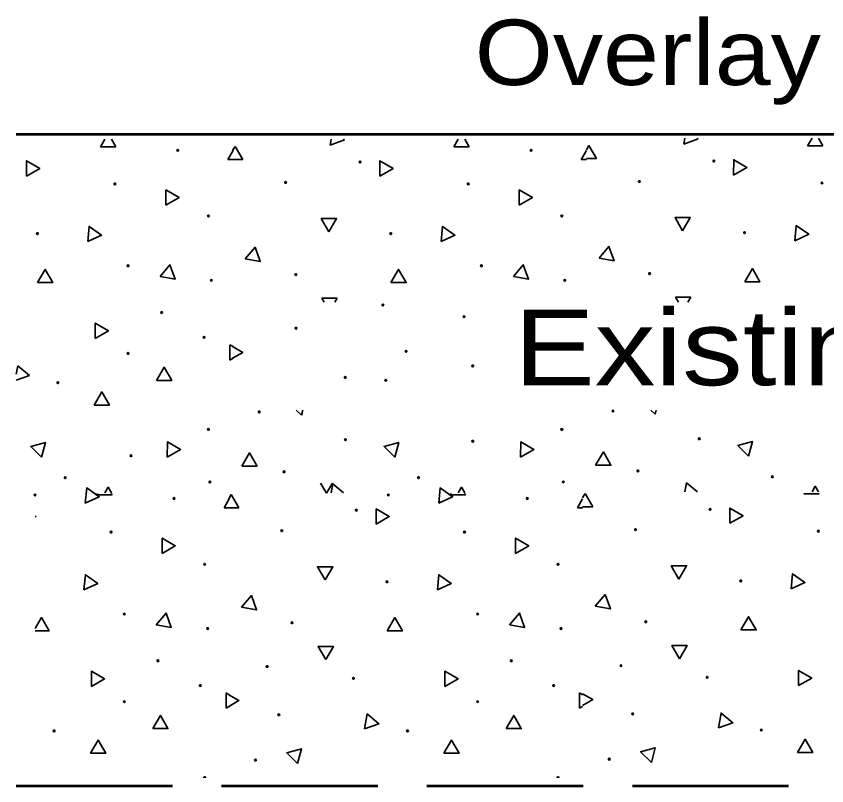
# Model space of a CAD drawing. Extents: x 72.6 to 107.3, y 36.1 to 58.1.
# Drawn here: x 90.018 to 91.667, y 53.319 to 54.886 of the extents above; entities that cross this region are included whole.
import ezdxf

# ---------------------------------------------------------------- set-up
doc = ezdxf.new("R2010")
doc.units = 0
doc.header["$LTSCALE"] = 0.053
doc.linetypes.add('LONG_DASHED', pattern=[7.5, 6, -1.5])
doc.layers.add('1', color=7, linetype='Continuous', lineweight=35)
doc.layers.add('3', color=7, linetype='Continuous', lineweight=13)

msp = doc.modelspace()

# ---------------------------------------------------------------- linework, layer by layer
at = {"layer": '1', "lineweight": 53}
msp.add_line((90.01767, 54.64575), (94.0285, 54.64575), dxfattribs=at)
at = {"layer": '1'}
for p, q in [((91.37875, 54.63742), (91.37658, 54.62525)), ((91.37875, 54.63742), (91.37658, 54.62525)), ((91.40575, 54.63592), (91.40392, 54.63742)), ((91.40575, 54.63592), (91.40392, 54.63742)), ((91.63742, 54.63742), (91.62842, 54.622)), ((91.63742, 54.63742), (91.62842, 54.622)), ((91.65958, 54.622), (91.65058, 54.63742)), ((91.65958, 54.622), (91.65058, 54.63742)), ((90.19825, 54.6355), (90.18925, 54.62008)), ((90.19825, 54.6355), (90.18925, 54.62008)), ((90.22042, 54.62008), (90.21142, 54.6355)), ((90.22042, 54.62008), (90.21142, 54.6355)), ((90.46308, 54.62067), (90.45808, 54.612)), ((90.46308, 54.62067), (90.45808, 54.612)), ((90.47858, 54.59383), (90.46308, 54.62067)), ((90.47858, 54.59383), (90.46308, 54.62067)), ((90.65875, 54.6355), (90.65658, 54.62333)), ((90.65875, 54.6355), (90.65658, 54.62333)), ((90.65658, 54.62333), (90.68575, 54.634)), ((90.65658, 54.62333), (90.68575, 54.634)), ((90.68575, 54.634), (90.68392, 54.6355)), ((90.68575, 54.634), (90.68392, 54.6355)), ((90.91742, 54.6355), (90.90842, 54.62008)), ((90.91742, 54.6355), (90.90842, 54.62008)), ((90.93958, 54.62008), (90.93058, 54.6355)), ((90.93958, 54.62008), (90.93058, 54.6355)), ((91.18308, 54.62258), (91.17808, 54.61392)), ((91.18308, 54.62258), (91.17808, 54.61392)), ((91.19858, 54.59575), (91.18308, 54.62258)), ((91.19858, 54.59575), (91.18308, 54.62258)), ((91.37658, 54.62525), (91.40575, 54.63592)), ((91.37658, 54.62525), (91.40575, 54.63592)), ((91.62842, 54.622), (91.65958, 54.622)), ((91.62842, 54.622), (91.65958, 54.622)), ((90.18925, 54.62008), (90.22042, 54.62008)), ((90.18925, 54.62008), (90.22042, 54.62008)), ((90.45892, 54.612), (90.44833, 54.59383)), ((90.45892, 54.612), (90.44833, 54.59383)), ((90.90842, 54.62008), (90.93958, 54.62008)), ((90.90842, 54.62008), (90.93958, 54.62008)), ((91.17808, 54.612), (91.1675, 54.59383)), ((91.17808, 54.612), (91.1675, 54.59383)), ((90.44833, 54.59383), (90.45892, 54.59383)), ((90.44833, 54.59383), (90.45892, 54.59383)), ((90.45808, 54.59383), (90.47858, 54.59383)), ((90.45808, 54.59383), (90.47858, 54.59383)), ((91.1675, 54.59383), (91.17808, 54.59383)), ((91.1675, 54.59383), (91.17808, 54.59383)), ((91.17808, 54.59575), (91.19858, 54.59575)), ((91.17808, 54.59575), (91.19858, 54.59575)), ((90.67075, 54.31158), (90.63967, 54.31158)), ((90.63967, 54.31158), (90.64442, 54.30333)), ((90.67075, 54.31158), (90.63967, 54.31158)), ((90.63967, 54.31158), (90.64442, 54.30333)), ((90.666, 54.30333), (90.67075, 54.31158)), ((90.666, 54.30333), (90.67075, 54.31158)), ((91.39075, 54.3135), (91.35967, 54.3135)), ((91.35967, 54.3135), (91.3655, 54.30333)), ((91.39075, 54.3135), (91.35967, 54.3135)), ((91.35967, 54.3135), (91.3655, 54.30333)), ((91.38483, 54.30333), (91.39075, 54.3135)), ((91.38483, 54.30333), (91.39075, 54.3135)), ((90.45275, 54.21683), (90.45258, 54.18575)), ((90.45275, 54.21683), (90.45258, 54.18575)), ((90.45275, 54.21683), (90.45258, 54.18575)), ((90.45275, 54.21683), (90.45258, 54.18575)), ((90.45892, 54.21325), (90.45275, 54.21683)), ((90.45892, 54.21325), (90.45275, 54.21683)), ((90.45892, 54.21325), (90.45275, 54.21683)), ((90.45892, 54.21325), (90.45275, 54.21683)), ((90.45258, 54.18575), (90.45892, 54.18933)), ((90.45258, 54.18575), (90.45892, 54.18933)), ((90.45258, 54.18575), (90.45892, 54.18933)), ((90.45258, 54.18575), (90.45892, 54.18933)), ((90.02075, 54.17417), (90.01767, 54.15683)), ((90.02075, 54.17417), (90.01767, 54.15683)), ((90.0445, 54.15433), (90.02075, 54.17417)), ((90.0445, 54.15433), (90.02075, 54.17417)), ((90.01767, 54.1445), (90.0445, 54.15433)), ((90.01767, 54.1445), (90.0445, 54.15433)), ((90.58733, 54.084), (90.598, 54.07333)), ((90.58733, 54.084), (90.598, 54.07333)), ((90.598, 54.07333), (90.60083, 54.084)), ((90.598, 54.07333), (90.60083, 54.084)), ((91.30925, 54.084), (91.318, 54.07525)), ((91.30925, 54.084), (91.318, 54.07525)), ((91.318, 54.07525), (91.32033, 54.084)), ((91.318, 54.07525), (91.32033, 54.084)), ((90.63708, 53.93542), (90.649, 53.91467)), ((90.63708, 53.93542), (90.649, 53.91467)), ((90.649, 53.91467), (90.66108, 53.93542)), ((90.649, 53.91467), (90.66108, 53.93542)), ((90.18342, 53.91433), (90.18158, 53.91125)), ((90.18342, 53.91433), (90.18158, 53.91125)), ((90.18342, 53.91433), (90.18158, 53.91125)), ((90.18342, 53.91433), (90.18158, 53.91125)), ((90.18158, 53.91125), (90.21275, 53.91125)), ((90.18158, 53.91125), (90.21275, 53.91125)), ((90.18158, 53.91125), (90.21275, 53.91125)), ((90.18158, 53.91125), (90.21275, 53.91125)), ((90.21275, 53.91125), (90.21092, 53.91433)), ((90.21275, 53.91125), (90.21092, 53.91433)), ((90.21275, 53.91125), (90.21092, 53.91433)), ((90.21275, 53.91125), (90.21092, 53.91433)), ((90.45542, 53.91183), (90.45042, 53.90317)), ((90.45542, 53.91183), (90.45042, 53.90317)), ((90.47092, 53.885), (90.45542, 53.91183)), ((90.47092, 53.885), (90.45542, 53.91183)), ((90.90258, 53.91433), (90.90075, 53.91125)), ((90.90258, 53.91433), (90.90075, 53.91125)), ((90.90075, 53.91125), (90.93192, 53.91125)), ((90.90075, 53.91125), (90.93192, 53.91125)), ((90.93192, 53.91125), (90.93008, 53.91433)), ((90.93192, 53.91125), (90.93008, 53.91433)), ((91.17542, 53.91375), (91.17042, 53.90508)), ((91.17542, 53.91375), (91.17042, 53.90508)), ((91.19092, 53.88692), (91.17542, 53.91375)), ((91.19092, 53.88692), (91.17542, 53.91375)), ((91.62142, 53.91433), (91.62075, 53.91317)), ((91.62142, 53.91433), (91.62075, 53.91317)), ((91.62075, 53.91317), (91.65192, 53.91317)), ((91.62075, 53.91317), (91.65192, 53.91317)), ((91.65192, 53.91317), (91.65125, 53.91433)), ((91.65192, 53.91317), (91.65125, 53.91433)), ((90.45125, 53.90317), (90.44067, 53.885)), ((90.45125, 53.90317), (90.44067, 53.885)), ((90.45125, 53.90317), (90.44067, 53.885)), ((90.45125, 53.90317), (90.44067, 53.885)), ((91.17042, 53.90317), (91.15983, 53.885)), ((91.17042, 53.90317), (91.15983, 53.885)), ((90.44067, 53.885), (90.45125, 53.885)), ((90.44067, 53.885), (90.45125, 53.885)), ((90.44067, 53.885), (90.45125, 53.885)), ((90.44067, 53.885), (90.45125, 53.885)), ((90.45042, 53.885), (90.47092, 53.885)), ((90.45042, 53.885), (90.47092, 53.885)), ((91.15983, 53.885), (91.17042, 53.885)), ((91.15983, 53.885), (91.17042, 53.885)), ((91.17042, 53.88692), (91.19092, 53.88692)), ((91.17042, 53.88692), (91.19092, 53.88692)), ((90.44508, 53.508), (90.44492, 53.47692)), ((90.44508, 53.508), (90.44492, 53.47692)), ((90.44508, 53.508), (90.44492, 53.47692)), ((90.44508, 53.508), (90.44492, 53.47692)), ((90.44508, 53.508), (90.44492, 53.47692)), ((90.44508, 53.508), (90.44492, 53.47692)), ((90.44508, 53.508), (90.44492, 53.47692)), ((90.44508, 53.508), (90.44492, 53.47692)), ((90.45125, 53.50442), (90.44508, 53.508)), ((90.45125, 53.50442), (90.44508, 53.508)), ((90.45125, 53.50442), (90.44508, 53.508)), ((90.45125, 53.50442), (90.44508, 53.508)), ((90.45125, 53.50442), (90.44508, 53.508)), ((90.45125, 53.50442), (90.44508, 53.508)), ((90.45125, 53.50442), (90.44508, 53.508)), ((90.45125, 53.50442), (90.44508, 53.508)), ((91.16425, 53.508), (91.16408, 53.47692)), ((91.16425, 53.508), (91.16408, 53.47692)), ((91.16425, 53.508), (91.16408, 53.47692)), ((91.16425, 53.508), (91.16408, 53.47692)), ((91.17042, 53.50442), (91.16425, 53.508)), ((91.17042, 53.50442), (91.16425, 53.508)), ((91.17042, 53.50442), (91.16425, 53.508)), ((91.17042, 53.50442), (91.16425, 53.508)), ((90.44492, 53.47692), (90.45125, 53.4805)), ((90.44492, 53.47692), (90.45125, 53.4805)), ((90.44492, 53.47692), (90.45125, 53.4805)), ((90.44492, 53.47692), (90.45125, 53.4805)), ((90.44492, 53.47692), (90.45125, 53.4805)), ((90.44492, 53.47692), (90.45125, 53.4805)), ((90.44492, 53.47692), (90.45125, 53.4805)), ((90.44492, 53.47692), (90.45125, 53.4805)), ((91.16408, 53.47692), (91.17042, 53.4805)), ((91.16408, 53.47692), (91.17042, 53.4805)), ((91.16408, 53.47692), (91.17042, 53.4805)), ((91.16408, 53.47692), (91.17042, 53.4805))]:
    msp.add_line(p, q, dxfattribs=at)
at = {"layer": '1', "linetype": 'LONG_DASHED', "lineweight": 53}
msp.add_line((90.01767, 53.31908), (94.0285, 53.31908), dxfattribs=at)
msp.add_line((90.01767, 53.31908), (94.0285, 53.31908), dxfattribs=at)
at = {"layer": '1', "lineweight": 53}
msp.add_lwpolyline([(90.01767, 54.64575), (94.0285, 54.64575), (97.54775, 54.52283)], dxfattribs=at)
msp.add_lwpolyline([(90.01767, 54.64575), (94.0285, 54.64575), (97.54775, 54.52283)], dxfattribs=at)
at = {"layer": '1'}
for points in [[(90.03858, 54.56033), (90.0655, 54.57583), (90.03875, 54.59142)], [(90.03858, 54.56033), (90.0655, 54.57583), (90.03875, 54.59142)], [(90.75775, 54.56033), (90.78467, 54.57583), (90.75792, 54.59142)], [(90.75775, 54.56033), (90.78467, 54.57583), (90.75792, 54.59142)], [(91.47775, 54.56225), (91.50467, 54.57775), (91.47792, 54.59333)], [(91.47775, 54.56225), (91.50467, 54.57775), (91.47792, 54.59333)], [(90.32225, 54.50083), (90.34917, 54.51642), (90.32242, 54.532)], [(90.32225, 54.50083), (90.34917, 54.51642), (90.32242, 54.532)], [(91.04142, 54.50083), (91.06833, 54.51642), (91.04158, 54.532)], [(91.04142, 54.50083), (91.06833, 54.51642), (91.04158, 54.532)], [(90.65392, 54.44692), (90.66958, 54.47383), (90.6385, 54.47383)], [(90.65392, 54.44692), (90.66958, 54.47383), (90.6385, 54.47383)], [(91.37392, 54.44883), (91.38958, 54.47575), (91.3585, 54.47575)], [(91.37392, 54.44883), (91.38958, 54.47575), (91.3585, 54.47575)], [(90.16325, 54.42675), (90.19142, 54.43983), (90.16608, 54.45767)], [(90.16325, 54.42675), (90.19142, 54.43983), (90.16608, 54.45767)], [(90.88242, 54.42675), (90.91058, 54.43983), (90.88525, 54.45767)], [(90.88242, 54.42675), (90.91058, 54.43983), (90.88525, 54.45767)], [(91.60242, 54.42867), (91.63058, 54.44175), (91.60525, 54.45958)], [(91.60242, 54.42867), (91.63058, 54.44175), (91.60525, 54.45958)], [(90.48392, 54.3915), (90.5145, 54.38608), (90.50392, 54.41525)], [(90.48392, 54.3915), (90.5145, 54.38608), (90.50392, 54.41525)], [(91.20392, 54.39342), (91.2345, 54.388), (91.22392, 54.41717)], [(91.20392, 54.39342), (91.2345, 54.388), (91.22392, 54.41717)], [(90.31042, 54.35575), (90.34092, 54.35033), (90.33033, 54.37958)], [(91.02958, 54.35575), (91.06008, 54.35033), (91.0495, 54.37958)], [(91.02958, 54.35575), (91.06008, 54.35033), (91.0495, 54.37958)], [(90.06108, 54.34333), (90.09217, 54.34333), (90.07675, 54.37017)], [(90.06108, 54.34333), (90.09217, 54.34333), (90.07675, 54.37017)], [(90.78025, 54.34333), (90.81133, 54.34333), (90.79592, 54.37017)], [(90.78025, 54.34333), (90.81133, 54.34333), (90.79592, 54.37017)], [(91.50025, 54.34525), (91.53133, 54.34525), (91.51592, 54.37208)], [(91.50025, 54.34525), (91.53133, 54.34525), (91.51592, 54.37208)], [(90.17842, 54.22992), (90.20533, 54.24542), (90.1785, 54.261)], [(90.17842, 54.22992), (90.20533, 54.24542), (90.1785, 54.261)], [(90.30308, 54.14433), (90.33408, 54.14433), (90.31867, 54.17117)], [(90.30308, 54.14433), (90.33408, 54.14433), (90.31867, 54.17117)], [(90.17633, 54.094), (90.20742, 54.094), (90.19192, 54.12083)], [(90.17633, 54.094), (90.20742, 54.094), (90.19192, 54.12083)], [(90.06908, 53.98792), (90.07708, 54.018), (90.04717, 54.01)], [(90.06908, 53.98792), (90.07708, 54.018), (90.04717, 54.01)], [(90.32508, 53.988), (90.35208, 54.0035), (90.32533, 54.019)], [(90.32508, 53.988), (90.35208, 54.0035), (90.32533, 54.019)], [(90.78825, 53.98792), (90.79625, 54.018), (90.76633, 54.01)], [(90.78825, 53.98792), (90.79625, 54.018), (90.76633, 54.01)], [(91.04425, 53.988), (91.07125, 54.0035), (91.0445, 54.019)], [(91.04425, 53.988), (91.07125, 54.0035), (91.0445, 54.019)], [(91.50825, 53.98983), (91.51625, 54.01992), (91.48633, 54.01192)], [(91.50825, 53.98983), (91.51625, 54.01992), (91.48633, 54.01192)], [(90.47692, 53.96983), (90.508, 53.96983), (90.49258, 53.99667)], [(90.47692, 53.96983), (90.508, 53.96983), (90.49258, 53.99667)], [(91.19692, 53.97175), (91.228, 53.97175), (91.21258, 53.99858)], [(91.19692, 53.97175), (91.228, 53.97175), (91.21258, 53.99858)], [(90.15833, 53.8945), (90.1865, 53.90758), (90.16117, 53.92542)], [(90.15833, 53.8945), (90.1865, 53.90758), (90.16117, 53.92542)], [(90.8775, 53.8945), (90.90567, 53.90758), (90.88033, 53.92542)], [(90.8775, 53.8945), (90.90567, 53.90758), (90.88033, 53.92542)], [(90.75008, 53.8515), (90.777, 53.867), (90.75025, 53.88258)], [(90.75008, 53.8515), (90.777, 53.867), (90.75025, 53.88258)], [(91.47008, 53.85342), (91.497, 53.86892), (91.47025, 53.8845)], [(91.47008, 53.85342), (91.497, 53.86892), (91.47025, 53.8845)], [(90.31458, 53.792), (90.3415, 53.80758), (90.31475, 53.82317)], [(90.31458, 53.792), (90.3415, 53.80758), (90.31475, 53.82317)], [(90.31458, 53.792), (90.3415, 53.80758), (90.31475, 53.82317)], [(90.31458, 53.792), (90.3415, 53.80758), (90.31475, 53.82317)], [(91.03375, 53.792), (91.06067, 53.80758), (91.03392, 53.82317)], [(91.03375, 53.792), (91.06067, 53.80758), (91.03392, 53.82317)], [(90.64625, 53.73808), (90.66192, 53.765), (90.63083, 53.765)], [(90.64625, 53.73808), (90.66192, 53.765), (90.63083, 53.765)], [(91.36625, 53.74), (91.38192, 53.76692), (91.35083, 53.76692)], [(91.36625, 53.74), (91.38192, 53.76692), (91.35083, 53.76692)], [(90.15558, 53.71792), (90.18375, 53.731), (90.15842, 53.74883)], [(90.15558, 53.71792), (90.18375, 53.731), (90.15842, 53.74883)], [(90.15558, 53.71792), (90.18375, 53.731), (90.15842, 53.74883)], [(90.15558, 53.71792), (90.18375, 53.731), (90.15842, 53.74883)], [(90.87475, 53.71792), (90.90292, 53.731), (90.87758, 53.74883)], [(90.87475, 53.71792), (90.90292, 53.731), (90.87758, 53.74883)], [(91.59475, 53.71983), (91.62292, 53.73292), (91.59758, 53.75075)], [(91.59475, 53.71983), (91.62292, 53.73292), (91.59758, 53.75075)], [(90.47625, 53.68267), (90.50683, 53.67725), (90.49625, 53.70642)], [(90.47625, 53.68267), (90.50683, 53.67725), (90.49625, 53.70642)], [(91.19625, 53.68458), (91.22683, 53.67917), (91.21625, 53.70833)], [(91.19625, 53.68458), (91.22683, 53.67917), (91.21625, 53.70833)], [(90.30275, 53.64692), (90.33325, 53.6415), (90.32267, 53.67075)], [(90.30275, 53.64692), (90.33325, 53.6415), (90.32267, 53.67075)], [(91.02192, 53.64692), (91.05242, 53.6415), (91.04183, 53.67075)], [(91.02192, 53.64692), (91.05242, 53.6415), (91.04183, 53.67075)], [(90.77258, 53.6345), (90.80367, 53.6345), (90.78825, 53.66133)], [(90.77258, 53.6345), (90.80367, 53.6345), (90.78825, 53.66133)], [(91.49258, 53.63642), (91.52367, 53.63642), (91.50825, 53.66325)], [(91.49258, 53.63642), (91.52367, 53.63642), (91.50825, 53.66325)], [(90.6475, 53.57583), (90.66308, 53.60275), (90.632, 53.60275)], [(90.6475, 53.57583), (90.66308, 53.60275), (90.632, 53.60275)], [(91.3675, 53.57775), (91.38308, 53.60467), (91.352, 53.60467)], [(91.3675, 53.57775), (91.38308, 53.60467), (91.352, 53.60467)], [(90.17075, 53.52108), (90.19767, 53.53658), (90.17083, 53.55217)], [(90.17075, 53.52108), (90.19767, 53.53658), (90.17083, 53.55217)], [(90.17075, 53.52108), (90.19767, 53.53658), (90.17083, 53.55217)], [(90.17075, 53.52108), (90.19767, 53.53658), (90.17083, 53.55217)], [(90.88992, 53.52108), (90.91683, 53.53658), (90.89, 53.55217)], [(90.88992, 53.52108), (90.91683, 53.53658), (90.89, 53.55217)], [(91.60992, 53.523), (91.63683, 53.5385), (91.61, 53.55408)], [(91.60992, 53.523), (91.63683, 53.5385), (91.61, 53.55408)], [(91.44683, 53.43675), (91.476, 53.44742), (91.45225, 53.46725)], [(91.44683, 53.43675), (91.476, 53.44742), (91.45225, 53.46725)], [(90.29542, 53.4355), (90.32642, 53.4355), (90.311, 53.46233)], [(90.29542, 53.4355), (90.32642, 53.4355), (90.311, 53.46233)], [(90.29542, 53.4355), (90.32642, 53.4355), (90.311, 53.46233)], [(90.29542, 53.4355), (90.32642, 53.4355), (90.311, 53.46233)], [(90.72683, 53.43483), (90.756, 53.4455), (90.73225, 53.46533)], [(90.72683, 53.43483), (90.756, 53.4455), (90.73225, 53.46533)], [(91.01458, 53.4355), (91.04558, 53.4355), (91.03017, 53.46233)], [(91.01458, 53.4355), (91.04558, 53.4355), (91.03017, 53.46233)], [(90.16867, 53.38517), (90.19975, 53.38517), (90.18425, 53.412)], [(90.16867, 53.38517), (90.19975, 53.38517), (90.18425, 53.412)], [(90.16867, 53.38517), (90.19975, 53.38517), (90.18425, 53.412)], [(90.16867, 53.38517), (90.19975, 53.38517), (90.18425, 53.412)], [(90.88783, 53.38517), (90.91892, 53.38517), (90.90342, 53.412)], [(90.88783, 53.38517), (90.91892, 53.38517), (90.90342, 53.412)], [(91.60783, 53.38708), (91.63892, 53.38708), (91.62342, 53.41392)], [(91.60783, 53.38708), (91.63892, 53.38708), (91.62342, 53.41392)], [(90.59033, 53.3645), (90.59833, 53.3945), (90.56842, 53.3865)], [(90.59033, 53.3645), (90.59833, 53.3945), (90.56842, 53.3865)], [(91.31033, 53.36642), (91.31833, 53.39642), (91.28842, 53.38842)], [(91.31033, 53.36642), (91.31833, 53.39642), (91.28842, 53.38842)]]:
    msp.add_lwpolyline(points, close=True, dxfattribs=at)
for points in [[(90.31042, 54.35575), (90.34092, 54.35033), (90.33033, 54.37958)], [(90.45808, 54.18933), (90.47867, 54.20133), (90.45808, 54.21325)], [(90.45808, 54.18933), (90.47867, 54.20133), (90.45808, 54.21325)], [(90.68392, 53.9155), (90.66208, 53.93383), (90.65875, 53.9155)], [(90.68392, 53.9155), (90.66208, 53.93383), (90.65875, 53.9155)], [(90.68392, 53.9155), (90.66208, 53.93383), (90.65875, 53.9155)], [(90.68392, 53.9155), (90.66208, 53.93383), (90.65875, 53.9155)], [(91.40392, 53.91742), (91.38208, 53.93575), (91.37875, 53.91742)], [(91.40392, 53.91742), (91.38208, 53.93575), (91.37875, 53.91742)], [(91.40392, 53.91742), (91.38208, 53.93575), (91.37875, 53.91742)], [(91.40392, 53.91742), (91.38208, 53.93575), (91.37875, 53.91742)], [(91.65058, 53.91742), (91.644, 53.92883), (91.63742, 53.91742)], [(91.65058, 53.91742), (91.644, 53.92883), (91.63742, 53.91742)], [(90.21142, 53.9155), (90.20483, 53.92692), (90.19825, 53.9155)], [(90.21142, 53.9155), (90.20483, 53.92692), (90.19825, 53.9155)], [(90.93058, 53.9155), (90.924, 53.92692), (90.91742, 53.9155)], [(90.93058, 53.9155), (90.924, 53.92692), (90.91742, 53.9155)], [(90.05625, 53.86608), (90.05783, 53.867), (90.05625, 53.86792)], [(90.05625, 53.86608), (90.05783, 53.867), (90.05625, 53.86792)], [(90.05625, 53.86608), (90.05783, 53.867), (90.05625, 53.86792)], [(90.05625, 53.86608), (90.05783, 53.867), (90.05625, 53.86792)], [(90.30275, 53.64692), (90.33325, 53.6415), (90.32267, 53.67075)], [(90.30275, 53.64692), (90.33325, 53.6415), (90.32267, 53.67075)], [(90.05625, 53.6345), (90.0845, 53.6345), (90.06908, 53.66133), (90.05625, 53.63933)], [(90.05625, 53.6345), (90.0845, 53.6345), (90.06908, 53.66133), (90.05625, 53.63933)], [(90.05625, 53.6345), (90.0845, 53.6345), (90.06908, 53.66133), (90.05625, 53.63933)], [(90.05625, 53.6345), (90.0845, 53.6345), (90.06908, 53.66133), (90.05625, 53.63933)], [(90.45042, 53.4805), (90.471, 53.4925), (90.45042, 53.50442)], [(90.45042, 53.4805), (90.471, 53.4925), (90.45042, 53.50442)], [(91.17042, 53.48242), (91.191, 53.49442), (91.17042, 53.50633)], [(91.17042, 53.48242), (91.191, 53.49442), (91.17042, 53.50633)]]:
    msp.add_lwpolyline(points, dxfattribs=at)
for centre in [(90.34642, 54.6127), (90.34642, 54.6127), (91.06558, 54.6127), (91.06558, 54.6127), (90.71752, 54.58888), (90.71752, 54.58888), (91.43752, 54.5908), (91.43752, 54.5908), (90.2185, 54.5443), (90.2185, 54.5443), (90.56578, 54.54724), (90.56578, 54.54724), (90.93766, 54.5443), (90.93766, 54.5443), (91.28578, 54.54916), (91.28578, 54.54916), (91.65766, 54.54622), (91.65766, 54.54622), (90.40894, 54.47884), (90.40894, 54.47884), (91.1281, 54.47884), (91.1281, 54.47884), (90.06082, 54.44314), (90.06082, 54.44314), (90.77998, 54.44314), (90.77998, 54.44314), (91.49998, 54.44506), (91.49998, 54.44506), (90.24532, 54.37768), (90.24532, 54.37768), (90.96448, 54.37768), (90.96448, 54.37768), (90.58666, 54.3598), (90.58666, 54.3598), (91.30666, 54.36172), (91.30666, 54.36172), (90.41488, 54.34792), (90.41488, 54.34792), (91.13404, 54.34792), (91.13404, 54.34792), (90.76401, 54.29775), (90.31372, 54.28246), (90.31372, 54.28246), (90.92917, 54.27417), (90.58701, 54.25059), (90.4, 54.23188), (90.4, 54.23188), (90.24532, 54.19918), (90.24532, 54.19918), (90.81117, 54.20342), (90.94684, 54.17384), (90.68726, 54.15025), (90.76984, 54.14434), (90.10252, 54.13966), (90.10252, 54.13966), (90.51226, 54.0802), (90.51226, 54.0802), (91.23226, 54.08212), (91.23226, 54.08212), (90.40894, 54.0445), (90.40894, 54.0445), (91.1281, 54.0445), (91.1281, 54.0445), (91.40776, 54.02554), (91.40776, 54.02554), (90.68776, 54.02362), (90.68776, 54.02362), (90.94684, 54.02042), (90.25126, 53.99092), (90.25126, 53.99092), (91.28284, 53.96014), (91.28284, 53.96014), (90.1174, 53.94628), (90.1174, 53.94628), (90.56284, 53.95822), (90.56284, 53.95822), (90.83656, 53.94628), (90.83656, 53.94628), (91.55656, 53.9482), (91.55656, 53.9482), (90.41188, 53.9374), (90.41188, 53.9374), (91.13104, 53.9374), (91.13104, 53.9374), (90.0559, 53.91089), (90.0559, 53.91089), (90.77507, 53.91089), (90.77507, 53.91089), (90.33875, 53.90387), (90.33875, 53.90387), (90.33875, 53.90387), (90.33875, 53.90387), (91.05792, 53.90387), (91.05792, 53.90387), (90.70986, 53.88005), (90.70986, 53.88005), (91.42986, 53.88196), (91.42986, 53.88196), (90.21083, 53.83547), (90.21083, 53.83547), (90.21083, 53.83547), (90.21083, 53.83547), (90.55812, 53.83841), (90.55812, 53.83841), (90.93, 53.83547), (90.93, 53.83547), (91.27812, 53.84032), (91.27812, 53.84032), (91.65, 53.83738), (91.65, 53.83738), (90.40127, 53.77001), (90.40127, 53.77001), (90.40127, 53.77001), (90.40127, 53.77001), (91.12044, 53.77001), (91.12044, 53.77001), (90.77232, 53.73431), (90.77232, 53.73431), (91.49232, 53.73622), (91.49232, 53.73622), (90.23765, 53.66885), (90.23765, 53.66885), (90.23765, 53.66885), (90.23765, 53.66885), (90.95682, 53.66885), (90.95682, 53.66885), (90.579, 53.65097), (90.579, 53.65097), (91.299, 53.65288), (91.299, 53.65288), (90.40721, 53.63909), (90.40721, 53.63909), (90.40721, 53.63909), (90.40721, 53.63909), (91.12638, 53.63909), (91.12638, 53.63909), (90.30605, 53.57363), (90.30605, 53.57363), (90.30605, 53.57363), (90.30605, 53.57363), (91.02522, 53.57363), (91.02522, 53.57363), (91.24842, 53.56366), (91.24842, 53.56366), (90.52842, 53.56175), (90.52842, 53.56175), (90.70392, 53.53793), (90.70392, 53.53793), (91.42392, 53.53984), (91.42392, 53.53984), (90.39233, 53.52305), (90.39233, 53.52305), (90.39233, 53.52305), (90.39233, 53.52305), (91.1115, 53.52305), (91.1115, 53.52305), (90.23765, 53.49035), (90.23765, 53.49035), (90.23765, 53.49035), (90.23765, 53.49035), (90.95682, 53.49035), (90.95682, 53.49035), (91.27218, 53.4655), (91.27218, 53.4655), (90.55218, 53.46359), (90.55218, 53.46359), (91.53402, 53.43274), (91.53402, 53.43274), (90.09485, 53.43083), (90.09485, 53.43083), (90.09485, 53.43083), (90.09485, 53.43083), (90.81402, 53.43083), (90.81402, 53.43083), (90.5046, 53.37137), (90.5046, 53.37137), (91.2246, 53.37328), (91.2246, 53.37328)]:
    msp.add_circle(centre, 0.00173, dxfattribs=at)
for centre in [(90.40127, 53.33567), (90.40127, 53.33567), (90.40127, 53.33567), (90.40127, 53.33567), (91.12044, 53.33567), (91.12044, 53.33567)]:
    msp.add_arc(centre, 0.00173, 340.24602, 199.75398, dxfattribs=at)

# ---------------------------------------------------------------- texts
at = {"layer": '3'}
for s, height, width, p in [('Overlay', 0.133, 1.15, (90.95075, 54.74558)), ('Existing  pavement', 0.1536, 1.2, (91.03067, 54.1345))]:
    msp.add_text(s, height=height, dxfattribs=dict(at, width=width)).set_placement(p)

doc.saveas('drawing.dxf')
